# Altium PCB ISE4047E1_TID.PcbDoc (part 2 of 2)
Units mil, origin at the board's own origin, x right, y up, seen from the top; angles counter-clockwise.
Board outline 2952.76 x 1377.95 mil, 4 copper layers (Layer 1 - Top Layer, Layer 2 - GND, Layer 3 - PWR, Layer 4 - Bottom Layer), stack 43.668 mil thick; 130 components, 47 nets, 287 pads, 266 vias.
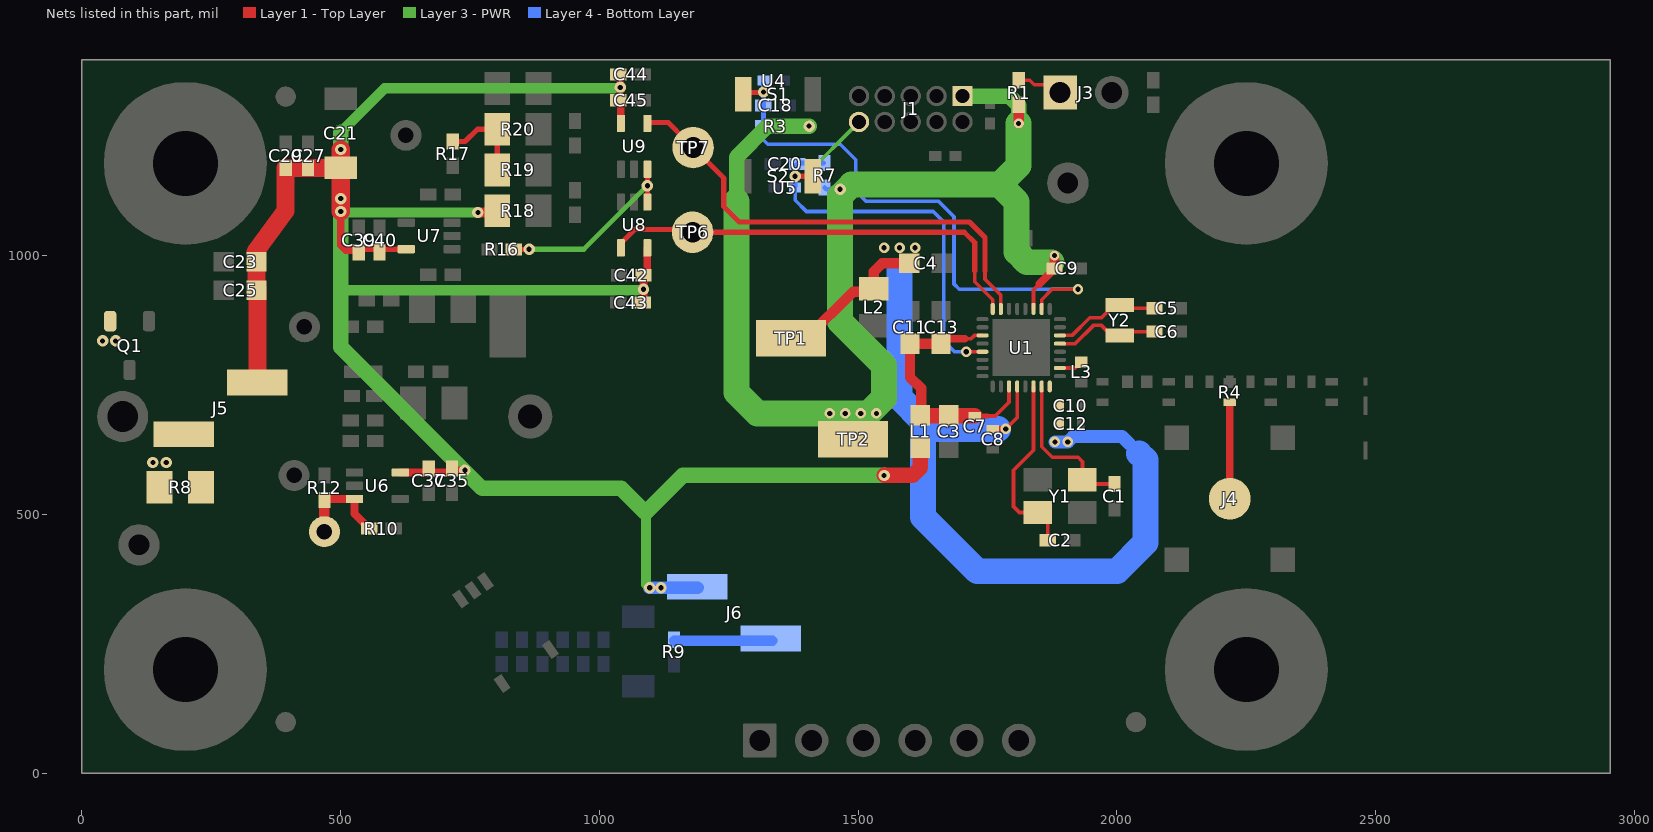
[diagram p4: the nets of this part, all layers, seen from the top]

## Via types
v1: diameter 20, hole 10, Layer 1 - Top Layer to Layer 4 - Bottom Layer, tented both sides, 198 vias
v2: diameter 22, hole 10, Layer 1 - Top Layer to Layer 4 - Bottom Layer, tented both sides, 52 vias
v3: diameter 19.68, hole 7.87, Layer 1 - Top Layer to Layer 4 - Bottom Layer, tented both sides, 16 vias

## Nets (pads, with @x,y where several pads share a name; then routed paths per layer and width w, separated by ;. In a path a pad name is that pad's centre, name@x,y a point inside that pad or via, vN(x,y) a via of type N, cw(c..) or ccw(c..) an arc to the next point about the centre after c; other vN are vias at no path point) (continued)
NetJ3_1: J3.1 R1.1 | length 89.8
  Layer 1 - Top Layer w7: R1.1@1810,1338.62 1831.38,1338.62 1840,1330 1875,1330 J3.1@1890,1315
NetJ4_1: J4.1 R4.2 | length 184.7
  Layer 1 - Top Layer w15: J4.1@2218,531.63 R4.2@2218,716.3
NetJ5_1: J5.1 R8.2
NetJ6_1: J6.1 R9.2 | length 189.6
  Layer 4 - Bottom Layer w20: R9.2@1144,255.69 J6.1@1333.62,255.69
NetL3_1: L3.1 U1.2 | length 45.8
  Layer 1 - Top Layer w7: U1.2@1889.8,782.63 1919.63,782.63 1930.7,793.7 L3.1@1931,793.7
NetQ1_2: Q1.2 R8.1
  other v2: 137,600 163,600 40,835 65,835
NetR10_2: pad.0@468.5,466.39 R10.2 R12.2 U6.3 | length 189
  Layer 1 - Top Layer w15: R12.2@468.5,527.56 470.47,529.53 U6.3@526.57,529.53 526.57,500.98 R10.2@555.12,472.44
  Layer 1 - Top Layer w20: pad.0@468.5,466.39 R12.2@468.5,527.56
NetR16_2: R16.2 U8.1 U9.3 | length 373.9
  Layer 1 - Top Layer w10: R16.2@834.65,1011.81 863.81,1011.81 v2(864,1012) ; U8.1@1092.52,1103.35 v2(1092.52,1135) U9.3@1092.52,1168.31
  Layer 3 - PWR w10: v2(864,1012) 969.52,1012 v2(1092.52,1135)
NetR17_2: R17.2 R19.1 R20.2 | length 174.5
  Layer 1 - Top Layer w10: R17.2@716.54,1220.47 740.47,1220.47 764.09,1244.09 R20.2@802.52,1244.09 R19.1@802.52,1165.35
NRESET: C20.2 J1.10 R7.1 S2.2 U1.21 U5.1 | length 942.4
  Layer 1 - Top Layer w7: v1(1708.75,814.13) U1.21@1740.2,814.13
  Layer 1 - Top Layer w10: v2(1378.09,1153.3) v2(1378.09,1153.3) S2.2@1411.93,1153.26
  Layer 3 - PWR w7: v2(1378.09,1153.3) 1396.53,1153.3 J1.10@1501.42,1258.19
  Layer 4 - Bottom Layer w7: U5.1@1378.05,1133.59 1378.05,1106.95 1400,1085 1645,1085 1665,1065 1665,835 1685.87,814.13 v1(1708.75,814.13)
  Layer 4 - Bottom Layer w10: U5.1@1378.05,1133.59 1378.05,1172.96 1383.96,1178.87 R7.1@1433.17,1178.87
PIR_OUT_HI: TP6.1 U1.16 U8.4 | length 850.4
  Layer 1 - Top Layer w7: 1725,970 1725,949.62 1759.88,914.74 U1.16@1759.88,896.8
  Layer 1 - Top Layer w10: U8.4@1041.34,1014.76 1041.34,1023.66 1067.68,1050 TP6.1@1175.98,1050 ; TP6.1@1180,1045 1705,1045 1725,1025 1725,970
PIR_OUT_LO: TP7.1 U1.15 U9.4 | length 905.8
  Layer 1 - Top Layer w7: 1745,970 1745,954.42 1775.63,923.79 U1.15@1775.63,896.8
  Layer 1 - Top Layer w10: U9.4@1092.52,1256.89 1132.87,1256.89 TP7.1@1165.87,1223.9 ; TP7.1@1181.1,1208.66 1240,1149.76 1240,1095 1270,1065 1715,1065 1745,1035 1745,970
USR_BTN: C18.2 R3.1 S1.2 U1.10 U4.1 | length 1087
  Layer 1 - Top Layer w7: U1.10@1854.37,896.8 1854.37,914.75 1874.62,935 v1(1924.62,935)
  Layer 1 - Top Layer w10: S1.2@1278.07,1312 1281.07,1315 1315.97,1315 v2(1316.97,1316)
  Layer 4 - Bottom Layer w7: R3.1@1316.38,1250 1316.38,1223.62 1325,1215 1465,1215 1495,1185 1495,1125 1515,1105 1655,1105 1685,1075 1685,945 1695,935 v1(1924.62,935)
  Layer 4 - Bottom Layer w10: R3.1@1316.97,1250 v2(1316.97,1316) U4.1@1316.97,1334.41
V_BATT: C21.1 C23.1 C25.1 C27.1 C29.1 C35.2 C37.1 C39.2 C40.1 C42.2 C43.1 C44.2 C45.1 J5.2 J6.2 L1.1 R18.2 U6.5 U7.5 U8.5 U9.5 | length 4605.7
  Layer 1 - Top Layer w10: C39.2@529.17,1010.31 531.13,1012.28 U7.5@626.61,1012.28
  Layer 1 - Top Layer w15: v2(500,1085) 500,1020 509.69,1010.31 C39.2@529.17,1010.31 ; U6.5@615.16,580.71 708.66,580.71 716.54,588.58 720.12,585 v2(740,585) ; R18.2@800.91,1085 R18.2@802.52,1086.61 ; C44.2@1040,1350 v2(1040,1325) 1040,1302.46 1041.85,1300.61 1041.34,1300.1 U9.5@1041.34,1256.89 ; C43.1@1083.62,905 1085,906.38 v2(1085,935) 1085.16,935.16 C42.2@1085.16,962.03 1092.52,969.39 U8.5@1092.52,1014.76
  Layer 1 - Top Layer w20: v2(765,1083.07) 798.98,1083.07 R18.2@802.52,1086.61
  Layer 1 - Top Layer w30: v2(1550,575) 1605,575 1620,590 L1.1@1620,628.5
  Layer 1 - Top Layer w35: 335,1006.89 393.7,1086.61 C29.1@393.7,1169.29 C21.1@500,1169.29 ; C25.1@337.28,933.07 C23.1@337.28,988.19 ; J5.2@339,768 C25.1@339,938.35 ; v2(500,1085) v2(500,1110) C21.1@500,1169.29 ; v2(500,1205) C21.1@500,1169.29
  Layer 3 - PWR w20: 500,933.07 v2@1085,933.07 ; v2@500,1083.07 v2(765,1083.07) ; 500,1238.07 585,1323.07 v2@1040,1323.07 ; v2@1090,365.07 1090,503
  Layer 3 - PWR w30: 500,1238.07 500,1083.07 500,933.07 500,823.07 773.07,550 1042,550 1089,503 1161,575 v2(1550,575)
  Layer 4 - Bottom Layer w25: v2(1097,358.07) v2(1119,358.07) J6.2@1189.14,358.07
VDDR: C4.2 C8.1 C10.1 C12.1 L2.2 TP1.1 U1.28 U1.32 | length 1898.5
  Layer 1 - Top Layer w7: v1(1785,665) 1807.13,687.13 U1.28@1807.13,747.2
  Layer 1 - Top Layer w12: C8.1@1760,665 v1(1785,665)
  Layer 1 - Top Layer w20: TP1.1@1395,840 1400,840 1490,930 1524.57,930 L2.2@1530,935.43 1530,969 1546,985 C4.2@1598.5,985
  Layer 4 - Bottom Layer w25: v1(1880,640) v1(1905,640) 1915,650 2010,650 2042.5,617.5
  Layer 4 - Bottom Layer w50: 1580,970 1580,725 1625,680 ; 1770,665 1640,665 1625,680 ; 2042.5,617.5 2055,605 2055,445 2000,390 1730,390 1625,495 1625,680
  other v1: 1550,1015 1580,1015 1610,1015
VDDS: C3.1 C7.1 C9.1 C11.2 C13.2 J1.1 L1.2 R1.2 R3.2 R7.2 TP2.1 U1.11 U1.19 U1.27 | length 2916.7
  Layer 1 - Top Layer w7: 1706,839 1718,839 1724.62,845.62 U1.19@1740.2,845.62 ; 1750,690 1765,690 1791.38,716.38 U1.27@1791.38,747.2 ; U1.11@1838.62,896.8 1838.62,933.62 1850,945
  Layer 1 - Top Layer w10: C7.1@1725,690 1750,690
  Layer 1 - Top Layer w15: C13.2@1660,829.5 1669.5,839 1706,839 ; 1850,945 1879.38,974.38 C9.1@1879.38,975
  Layer 1 - Top Layer w20: L1.2@1621.5,690 1621.5,743.5 1600,765 C11.2@1600,829.5 C13.2@1660,829.5 ; v1(1810,1255) R1.2@1810,1291.38 ; C9.1@1879.38,975 v1(1879.38,1000)
  Layer 1 - Top Layer w30: L1.2@1621.5,690 C7.1@1725,690
  Layer 3 - PWR w30: 1265,1105 1265,1190 1325,1250 v2(1405,1250) ; J1.1@1701.42,1308.19 1791.81,1308.19 1810,1290 v1(1810,1255)
  Layer 3 - PWR w50: 1265,1105 1265,735 1305,695 1520,695 1550,725 1550,787 1465,872 1465,1115 1487,1137 1773,1137 ; v1(1810,1255) 1810,1174 1773,1137 ; 1874,987 1826,987 1806,1007 1806,1104 1773,1137
  Layer 4 - Bottom Layer w9: R7.2@1435,1131.38 1438.38,1128 v2(1465,1128)
  Layer 4 - Bottom Layer w10: R3.2@1363.62,1250 v2(1405,1250)
  other v1: 1445,695 1475,695 1505,695 1535,695
X24M_N: C2.2 U1.30 Y1.3 | length 361.3
  Layer 1 - Top Layer w7: U1.30@1838.62,747.2 1838.62,623.62 1800,585 1800,515 1811.5,503.5 Y1.3@1846.69,503.5 1866.38,483.82 C2.2@1866.38,450
X24M_P: C1.2 U1.31 Y1.1 | length 307.6
  Layer 1 - Top Layer w7: U1.31@1854.37,747.2 1854.37,630.63 1875,610 1925,610 1933.31,601.69 Y1.1@1933.31,566.5 1941.18,558.62 C1.2@1995,558.62
X32K_Q1: C6.1 U1.5 Y2.1 | length 208
  Layer 1 - Top Layer w7: U1.5@1889.8,829.87 1919.5,829.87 1954.62,865 1969.62,865 ; 1970,865 1989.53,845.47 Y2.1@2005,845.47 2012.53,853 C6.1@2072.38,853
X32K_Q2: C5.1 U1.6 Y2.2 | length 209.3
  Layer 1 - Top Layer w7: U1.6@1889.8,845.62 1912.97,845.62 1947.35,880 1969.62,880 ; 1970,880 1994.53,904.53 Y2.2@2005,904.53 2011.53,898 C5.1@2072.38,898
pads on no net: FID1.1 FID2.1 FID3.1 FID4.1 FID5.1 FID6.1 H1.0 H7.0 J1.6 J1.7 J1.8 SH-J1.0 SH-J2.0 SH-J3.0 U1.4 U1.8 U1.22

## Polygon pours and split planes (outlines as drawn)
GND on Layer 1 - Top Layer "Layer 1 - Top Layer - GND" (solid, remove dead copper, pour order 2): 20,20 2464.57,20 2464.57,1355 20,1355
GND on Layer 2 - GND "Layer 2 - GND - GND" (solid, remove dead copper, pour order 4): 20,20 2464.57,20 2464.57,1355 20,1355
GND on Layer 3 - PWR "Layer 3 - PWR - GND" (solid, remove dead copper, pour order 6): 20,20 2464.57,20 2464.57,1355 20,1355
GND on Layer 4 - Bottom Layer "Layer 4 - Bottom Layer - GND" (solid, remove dead copper, pour order 8): 20,1355 20,20 2464.57,20 2464.57,1355

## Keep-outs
Keep-Out Layer:
  lines w10: -5,0 ccw(c0,0) 0,-5 ; -5,0 ccw(c0,0) 0,-5 ; -5,0 -5,1377.95 ; -5,1377.95 cw(c0,1377.95) 0,1382.95 ; -5,1377.95 cw(c0,1377.95) 0,1382.95 ; 0,-5 2952.76,-5 ; 0,1382.95 2952.76,1382.95 ; 2952.76,-5 ccw(c2952.76,0) 2957.76,0 ; 2952.76,-5 ccw(c2952.76,0) 2957.76,0 ; 2952.76,1382.95 cw(c2952.76,1377.95) 2957.76,1377.95 ; 2952.76,1382.95 cw(c2952.76,1377.95) 2957.76,1377.95 ; 2957.76,0 2957.76,1377.95
  text ".Layer_Name" at 577,-858.49 h60

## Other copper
Layer 1 - Top Layer:
  rectangle net NetBT1_1: 51.18,690 105,800
  rectangle net NetJ5_1: 205,559 255,679
  rectangle net NetQ1_2: 25,820 80,895
  rectangle net NetQ1_2: 125,520 175,611
  pour cut-out: 2050,370 2380,370 2380,695 2050,695
  pour cut-out: 1490,870 1755,870 1755,980 1700,1035 1490,1035
  region net GND: 1578,873 1578,933 1595,950 1625,950 1640,965 1640,1005 1685,1005 1705,985 1705,926 1752,879 1759,879 1762,876 1762,866 1755,873
  pour cut-out: 1727.4,734.8 1902.6,734.8 1902.6,910 1727.4,910
  pour cut-out: 2464.57,0 2952.76,0 2952.76,1377.95 2464.57,1377.95
  region net GND: 1895,435 1895,530 2010,530 2010,455 1990,435
  region net GND: 2464.57,780.77 2464.57,1355 2415,1355 2415,820 1960,820 1960,780.77
  region net GND: 2464.57,20 2415,20 2415,730 2464.57,730
  region net VDDS: 1570,610 1570,650 1585,665 1695,665 1710,680 1710,700 1695,715 1535,715 1445,715 1420,690 1420,610
  region net GND: 2480,604.06 2460.94,604.06 2455,610 2455,635 2462.43,642.43 2480,642.43
  region net GND: 2480,690.68 2459.32,690.68 2455,695 2455,720 2464.05,729.05 2480,729.05
  region net NetC15_1: 1974,744.3 1919,744.3 1919,768.3 1974,768.3
  region net NetC17_1: 2223,744.3 2230,744.3 2230,768.3 2223,768.3
  region net VDDR: 1866,759 1866,639 1875,630 1910,630 1915,635 1915,645 1900,660 1900,731 1872,759
  pour cut-out: 1833,760 1833,678 1785,630 1785,485 1835,435 1990,435 2010,455 2010,590 1985,615 1876,615 1859,632 1859,760 1869,760 1869,636 1880,625 1990,625 2020,595 2020,450 1995,425 1830,425 1775,480 1775,635 1823,683 1823,760 1823,769 1869,769 1869,760
  pour cut-out: 1725,725 1442.76,725 1407.76,690 1407.76,757.76 1485,835 1725,835
  pour cut-out: 2464.57,730 2242,730 2242,572 2240,570 2200,570 2194,576 2194,730 1916,730 1908,738 1908,763 1925.77,780.77 2464.57,780.77
  pour cut-out: 1020,1145 1115,1145 1115,1285 1020,1285
  pour cut-out: 1019.93,993.05 1114.93,993.05 1114.93,1133.05 1019.93,1133.05
  region net VDDR: 1620,965 1620,1020 1615,1025 1545,1025 1500,980 1500,910 1560,910 1560,945 1580,965
  text ".Layer_Name" at 577,-858.49 h60
Layer 2 - GND:
  pour cut-out: 2464.57,0 2952.76,0 2952.76,1377.95 2464.57,1377.95
  region net GND: 1990,435 1835,435 1785,485 1785,630 1815,660 1815,760 1859,760 1859,632 1876,615 1985,615 2010,590 2010,455
  pour cut-out: 1815,760 1815,660 1785,630 1785,485 1835,435 1990,435 2010,455 2010,590 1985,615 1876,615 1859,632 1859,760 1869,760 1869,636 1880,625 1990,625 2020,595 2020,450 1995,425 1830,425 1775,480 1775,635 1805,665 1805,769 1869,769 1869,760
  text ".Layer_Name" at 577,-858.49 h60
Layer 3 - PWR:
  rectangle net V_BATT: 1080,342.93 1134.14,378.07
  pour cut-out: 2464.57,0 2952.76,0 2952.76,1377.95 2464.57,1377.95
  region net NetQ1_2: 25,830 85,770 110,770 150,730 150,650 120,620 120,585 205,585 205,760 110,855 25,855
  pour cut-out: 1815,760 1815,660 1785,630 1785,485 1835,435 1990,435 2010,455 2010,590 1985,615 1876,615 1859,632 1859,760 1869,760 1869,636 1880,625 1990,625 2020,595 2020,450 1995,425 1830,425 1775,480 1775,635 1805,665 1805,769 1869,769 1869,760
  text ".Layer_Name" at 577,-858.49 h60
Layer 4 - Bottom Layer:
  pour cut-out: 2464.57,0 2952.76,0 2952.76,1377.95 2464.57,1377.95
  pour cut-out: 1815,760 1815,660 1785,630 1785,485 1835,435 1990,435 2010,455 2010,590 1985,615 1876,615 1859,632 1859,760 1869,760 1869,636 1880,625 1990,625 2020,595 2020,450 1995,425 1830,425 1775,480 1775,635 1805,665 1805,769 1869,769 1869,760
  region net VDDR: 1560,955 1540,975 1540,1025 1620,1025 1620,975 1600,955
  text ".Layer_Name" at 577,-858.49 h60

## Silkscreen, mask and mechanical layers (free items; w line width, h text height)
Top Overlay:
  text ".TID" at 1399.51,300.82 h60
  text ".PRJ_Number" at 1399.51,249.64 h60
  text ".PCB_Rev" at 1635.73,249.64 h60
  text ".Layer_Name" at 577,-858.49 h60
Bottom Overlay:
  text ".Layer_Name" at 577,-858.49 h60
Top Paste:
  text ".Layer_Name" at 577,-858.49 h60
Bottom Paste:
  text ".Layer_Name" at 577,-858.49 h60
Top Solder:
  text ".Layer_Name" at 577,-858.49 h60
  text ".Layer_Name" at 577,-858.49 h60
Bottom Solder:
  text ".Layer_Name" at 577,-858.49 h60
Drill Guide:
  text ".Layer_Name" at 577,-858.49 h60
M1 Board Outline:
  the board outline again, w10
  text "SLOT" at 980,290 h40 r30.14
  text "SLOT" at 635,90 h40 r30.14
  text ".Layer_Name" at 577,-858.49 h60
M2 Board Dimensions:
  rectangle: 125,-400 500,-275
  rectangle: 0,-275 125,-150
  lines w7: 0,-275 1000,-275 ; 125,-400 125,-150 ; 250,-400 250,-150 ; 500,-400 500,-150 ; 750,-400 750,-150 ; 0,-400 0,-150 1000,-150 1000,-400 0,-400
  text ".Layer_Name" at 577,-858.49 h60
M3 3D STEP Top:
  text ".Layer_Name" at 577,-858.49 h60
M4 3D STEP Bottom:
  text ".Layer_Name" at 577,-858.49 h60
M5 Assembly Top:
  lines w10: -292,-930.17 6308,-930.17 ; -292,-726.83 6310,-726.83 ; -292,-523.5 -292,-1133.5 3713,-1133.5 6310,-1133.5 6310,-523.5 -291.5,-523.5 -291.5,-1133.5 1284,-1133.5 ; 2173,-1133.5 2173,-523.5 ; 3440,-726.83 3440,-523.5 ; 4280,-726.83 4280,-523.5 ; 4902,-1140 4902,-937.17
  text "COMPONENTS MARKED 'DNP' SHOULD NOT BE POPULATED." at 1153.5,-318.5 h60
  text "ASSEMBLY VARIANT:" at 1153,-434 h60
  text ".VariantName" at 2189,-434 h60
  text "PCB VIEWED FROM TOP SIDE" at -228.5,-655.67 h60
  text "BOARD #:" at 2248,-655.67 h60
  text ".PRJ_Number" at 2793.5,-655.67 h60
  text "REV:" at 3638,-655.67 h60
  text ".PCB_Rev" at 3929.5,-655.67 h60
  text "SVN REV:" at 4476,-655.67 h60
  text ".VersionControl_RevNumber" at 4982,-655.67 h60
  text "TID #:" at 2248,-859 h60
  text ".TID" at 2793.5,-859 h60
  text "PLOT NAME =" at -228.5,-1064.34 h60
  text ".plot_File_Name" at 577,-1064.34 h60
  text "GENERATED    :" at 2250,-1064.34 h60
  text ".Print_Date" at 3119.5,-1064.34 h60
  text ".Print_Time" at 3848.5,-1064.34 h60
  text "TEXAS INSTRUMENTS" at 5113,-1064.34 h60
M6 Assembly Bottom:
  lines w10: -292.5,-727.33 6309.5,-727.33 ; -290.5,-930.67 6309.5,-930.67 ; 1115.5,-1140.5 1115.5,-937.67 ; 1737.5,-727.33 1737.5,-524 ; 2577.5,-727.33 2577.5,-524 ; 3844.5,-1134 3844.5,-524 ; 4733.5,-1134 6309,-1134 6309,-524 -292.5,-524 -292.5,-1134 2304.5,-1134 6309.5,-1134 6309.5,-524
  text "COMPONENTS MARKED 'DNP' SHOULD NOT BE POPULATED." at 6102,-318 h60
  text ".VariantName" at 5058,-434 h60
  text "ASSEMBLY VARIANT:" at 6097,-434 h60
  text ".VersionControl_RevNumber" at 1035.5,-656.17 h60
  text "SVN REV:" at 1541.5,-656.17 h60
  text ".PCB_Rev" at 2088,-656.17 h60
  text "REV:" at 2379.5,-656.17 h60
  text ".PRJ_Number" at 3224,-656.17 h60
  text "BOARD #:" at 3769.5,-656.17 h60
  text "PCB VIEWED FROM BOTTOM SIDE" at 6246,-656.17 h60
  text ".TID" at 3224,-859.5 h60
  text "TID #:" at 3769.5,-859.5 h60
  text "TEXAS INSTRUMENTS" at 904.5,-1064.84 h60
  text ".Print_Time" at 2169,-1064.84 h60
  text ".Print_Date" at 2898,-1064.84 h60
  text "GENERATED    :" at 3767.5,-1064.84 h60
  text ".plot_File_Name" at 5440.5,-1064.84 h60
  text "PLOT NAME =" at 6246,-1064.84 h60
M9 Title Sheet:
  drawing of 57 lines, arcs and shapes, not listed
  text "1" at 739.84,8036.5 h70
  text "2" at 3235.5,8036.5 h70
  text "3" at 5724.84,8036.5 h70
  text "4" at 8231.51,8036.5 h70
  text "5" at 10730.5,8036.5 h70
  text "6" at 13235.5,8036.5 h70
  text "A" at -416.5,6893.5 h70
  text "A" at 14383.5,6893.5 h70
  text "B" at -416.5,4513.5 h70
  text "B" at 14383.5,4513.5 h70
  text "C" at -416.5,2138.5 h70
  text "C" at 14383.5,2138.5 h70
  text "PROJECT TITLE:" at 11343.5,277.5 h45
  text ".PRJ_Title" at 11393.5,144.17 h70
  text "DESIGNED FOR:" at 11343.5,-23.5 h45
  text ".PRJ_Customer" at 11393.5,-163.5 h70
  text "D" at -416.5,-231.5 h70
  text "D" at 14383.5,-231.5 h70
  text "FILE NAME:" at 11343.5,-323.5 h45
  text ".PCB_File_Name_No_Path" at 11393.5,-443.5 h70
  text "Texas Instruments (TI) and/or its licensors do not warrant the accuracy or completeness of this specification" at 6374,-605.34 h45
  text "ENGINEER:" at 11343.5,-613.5 h45
  text "LAYOUT BY:" at 12848.5,-613.5 h45
  text "or any information contained therein. TI and/or its licensors do not warrant that this design will meet" at 6329.01,-718 h45
  text ".PRJ_Engineer" at 11393.5,-768.49 h70
  text ".PCB_Layout" at 12899,-768.49 h70
  text "the specifications, will be suitable for your application or fit for any particular purpose, or will operate in" at 6329.01,-830.67 h45
  text ".Layer_Name" at 577,-858.49 h60
  text "ALTIUM DESIGNER VERSION:" at 12848.5,-923.5 h45
  text "an implementation. TI and/or its licensors do not warrant that the design is production worthy. You should" at 6329.01,-943.33 h45
  text "completely validate and test your design implementation to confirm the system functionality for your application." at 6374,-1056 h45
  text ".print_Scale" at 11393.5,-1056.83 h70
  text ".Application_BuildNumber" at 12899,-1056.83 h70
  text "1" at 739.84,-1263.5 h70
  text "2" at 3235.5,-1263.5 h70
  text "3" at 5724.84,-1263.5 h70
  text "4" at 8231.51,-1263.5 h70
  text "5" at 10730.5,-1263.5 h70
  text "6" at 13235.5,-1263.5 h70
M10 Fab Notes:
  drawing of 186 lines, arcs and shapes, not listed
  text "DESIGN INFORMATION" at 12381.02,5910 h60
  text "MIN. TRACK WIDTH:" at 11736.46,5730 h60
  text "6" at 12832.7,5730 h60
  text "MIL" at 12987.46,5730 h60
  text "Impedance Control:" at 6857,5615 h200
  text "MIN. CLEARANCE:" at 11736.46,5598 h60
  text "mm" at 12987.46,5598 h60
  text "6" at 12830,5595 h60
  text "MIN. VIA PAD SIZE:" at 11736.46,5466 h60
  text "20" at 12802.71,5466 h60
  text "MIL" at 12987.46,5466 h60
  text "- Top layer contains 50 ohm impedance (+/- 10%) single ended using 24 mil lines (from E1 to U1)" at 6857,5375 h100
  text "0.05mm (2MIL)" at 12431.46,5324.29 h60
  text "MINIMUM ANNULAR RING" at 11407.23,5320 h60
  text "EXTERNAL" at 13139.46,5320 h60
  text "PER" at 11607.23,5202 h60
  text "IPC-D-275 CLASS 2 LEVEL C" at 11827.23,5202 h60
  text "MIL, HOLES" at 13315.46,5089.71 h60
  text "+/-" at 12923,5089 h60
  text "+/-" at 13777,5089 h60
  text "REGISTRATION TOLERANCES:" at 11407.23,5084 h60
  text "METAL" at 12607,5084 h60
  text "5" at 13183.2,5084 h60
  text "3" at 14016.2,5084 h60
  text "MIL" at 14132.46,5084 h60
  text "MATERIAL:" at 11332.46,4874.54 h60
  text "FR-4 High Tg" at 12318.9,4734.21 h60
  text "FR-408" at 11753.46,4725.64 h60
  text "X" at 12165.46,4725.64 h60
  text "OTHER" at 13241.46,4725.64 h60
  text "62 MIL (1.6mm) +/-10%" at 12073.56,4562.92 h60
  text "THICKNESS:" at 11407.23,4558.64 h60
  text "31 MIL (0.8mm) +/-10%" at 13348.56,4557.92 h60
  text "X" at 13230,4550 h60
  text "TOLERANCE:" at 11407.23,4400.64 h60
  text "X" at 12246.53,4400.64 h60
  text "ANSI IPC-6012 TYPE 3 CLASS 2" at 12433.48,4400.64 h60
  text "OTHER +/-" at 12433.46,4244.64 h60
  text "BOW & TWIST:" at 11407.23,4087.64 h60
  text "X" at 12246.53,4087.64 h60
  text "ANSI IPC-6012 TYPE 3 CLASS 2" at 12433.48,4087.64 h60
  text "OTHER +/-" at 12433.46,3929.13 h60
  text "DRILLING:" at 11332.46,3790.64 h60
  text "REFERENCE:" at 11407.23,3673.64 h60
  text "X" at 12055.46,3673.64 h60
  text "AS SHOWN" at 12242.46,3673.64 h60
  text "X" at 12956.46,3673.64 h60
  text "NC_DRILL FILES" at 13093.46,3673.64 h60
  text "PTH MIN COPPER THICKNESS:" at 11407.23,3515.64 h60
  text "X" at 12757.46,3515.64 h60
  text "1MIL" at 12894.46,3515.64 h60
  text "OTHER" at 13391.46,3515.64 h60
  text "BOARD FINISH:" at 11332.46,3356.64 h60
  text "SILKSCREEN:" at 11487.68,3238.64 h60
  text "X" at 12436.46,3238.64 h60
  text "TOP" at 12562.46,3238.64 h60
  text "X" at 12946.46,3238.64 h60
  text "BOTTOM" at 13073.46,3238.64 h60
  text "SILKSCREEN COLOR:" at 11487.68,3071.64 h60
  text "X" at 12435.42,3071.64 h60
  text "WHITE" at 12562.46,3071.64 h60
  text "OTHER" at 13073.46,3071.64 h60
  text "SOLDER RESIST COLOR:" at 11487.68,2901.64 h60
  text "X" at 12055.42,2742.44 h60
  text "GREEN" at 12182.46,2742.44 h60
  text "BLUE" at 12773.46,2742.44 h60
  text "OTHER" at 13311.46,2742.44 h60
  text "IMMERSION GOLD (ENIG)" at 12393.46,2553.92 h60
  text "ENEPIG" at 13731,2550.64 h60
  text "SURFACE FINISH:" at 11332.46,2549.64 h60
  text "X" at 12206.51,2549.64 h60
  text "IMM. TIN/SILVER OR EQUIV" at 11662,2392.64 h60
  text "OTHER" at 13093.46,2392.64 h60
  text "ARRAY/PANEL:" at 11332.46,2213.64 h60
  text "CUT AND TRIM PER MECH LAYER 1" at 12393.46,2209.35 h60
  text "N.C. ROUTE" at 12393.46,2057.64 h60
  text "X" at 13072.46,2057.64 h60
  text "V. SCORE" at 13259.46,2057.64 h60
  text "CERTIFICATION:" at 11332.46,1920.64 h60
  text "MATERIALS AND WORKMANSHIP FOR ALL PCBS" at 12057.46,1920.64 h60
  text "TO MEET OR EXCEED THE REQUIREMENTS OF:" at 12057.46,1822.64 h60
  text "X" at 11683.96,1686.13 h60
  text "ANSI IPC-A-600F CLASS ->" at 11822.96,1686.13 h60
  text "X" at 13462.02,1686.13 h60
  text "2" at 13580.96,1686.14 h60
  text "1" at 13265.96,1684.64 h60
  text "3" at 13934.96,1684.64 h60
  text "X" at 11686.02,1526.64 h60
  text "UL 94V-0" at 11822.96,1526.64 h60
  text "X" at 12498.02,1526.64 h60
  text "RoHS" at 12634.96,1526.64 h60
  text "OTHER" at 13279.36,1526.64 h60
  text "PER ORDER" at 13676.42,1526.64 h60
  text "ADDITIONAL REQUIREMENTS:" at 11332.46,1385.64 h60
  text "MICROSECTION:" at 11407.23,1270.64 h60
  text "YES" at 12312.96,1270.64 h60
  text "REQUIRED" at 13174.46,1114.49 h60
  text "BARE BOARD ELEC. TEST:" at 11407.23,1111.64 h60
  text "NONE" at 12712.96,1111.64 h60
  text "X" at 13047.46,1111.64 h60
  text "PER ORDER" at 13766.46,1111.64 h60
  text "MANUFACTURER'S UL:" at 11407.23,954.64 h60
  text "RAIL" at 12572.96,950.35 h60
  text "METAL" at 13064.77,950.35 h60
  text "X" at 13440,950 h60
  text "SILK" at 13576.46,950.35 h60
  text ".Layer_Name" at 577,-858.49 h60
M11 Gerber Information:
  lines w10: -292,-930.17 6308,-930.17 ; -292,-726.83 6310,-726.83 ; -292,-523.5 -292,-1133.5 3713,-1133.5 6310,-1133.5 6310,-523.5 -291.5,-523.5 -291.5,-1133.5 1284,-1133.5 ; 2173,-1133.5 2173,-523.5 ; 3440,-726.83 3440,-523.5 ; 4280,-726.83 4280,-523.5 ; 4902,-1140 4902,-937.17
  text "ALL ARTWORK VIEWED FROM TOP SIDE" at -228.5,-655.67 h60
  text "BOARD #:" at 2248,-655.67 h60
  text ".PRJ_Number" at 2793.5,-655.67 h60
  text "REV:" at 3638,-655.67 h60
  text ".PCB_Rev" at 3929.5,-655.67 h60
  text "SVN REV:" at 4476,-655.67 h60
  text ".VersionControl_RevNumber" at 4982,-655.67 h60
  text "LAYER NAME =" at -228.5,-858.49 h60
  text "TID #:" at 2248,-859 h60
  text ".TID" at 2793.5,-859 h60
  text "PLOT NAME =" at -228.5,-1064.34 h60
  text ".plot_File_Name" at 577,-1064.34 h60
  text "GENERATED    :" at 2250,-1064.34 h60
  text ".Print_Date" at 3119.5,-1064.34 h60
  text ".Print_Time" at 3848.5,-1064.34 h60
  text "TEXAS INSTRUMENTS" at 5113,-1064.34 h60
M12 Stackup:
  drawing of 295 lines, arcs and shapes, not listed
  text "Layer" at 9315,7840 h60
  text "Name" at 9724.91,7840 h60
  text "Material" at 11134.5,7840 h60
  text "Thickness" at 11994.27,7840 h60
  text "Constant" at 12644.1,7840 h60
  text "Board Layer Stack" at 13213.97,7840 h60
  text "1" at 9315,7720 h60
  text "Top Overlay" at 9724.91,7720 h60
  text "2" at 9315,7600 h60
  text "Top Solder" at 9724.91,7600 h60
  text "Solder Resist" at 11134.5,7600 h60
  text "0.40mil" at 11994.27,7600 h60
  text "3.5" at 12644.1,7600 h60
  text "3" at 9315,7480 h60
  text "Layer 1 - Top Layer" at 9724.91,7480 h60
  text "Copper" at 11134.5,7480 h60
  text "1.42mil" at 11994.27,7480 h60
  text "4" at 9315,7360 h60
  text "Dielectric 1" at 9724.91,7360 h60
  text "370HR" at 11134.5,7360 h60
  text "14.00mil" at 11994.27,7360 h60
  text "4.2" at 12644.1,7360 h60
  text "5" at 9315,7240 h60
  text "Layer 2 - GND" at 9724.91,7240 h60
  text "Copper" at 11134.5,7240 h60
  text "1.42mil" at 11994.27,7240 h60
  text "6" at 9315,7120 h60
  text "Dielectric 2" at 9724.91,7120 h60
  text "370HR" at 11134.5,7120 h60
  text "10.00mil" at 11994.27,7120 h60
  text "4.2" at 12644.1,7120 h60
  text "7" at 9315,7000 h60
  text "Layer 3 - PWR" at 9724.91,7000 h60
  text "Copper" at 11134.5,7000 h60
  text "1.42mil" at 11994.27,7000 h60
  text "8" at 9315,6880 h60
  text "Dielectric 3" at 9724.91,6880 h60
  text "370HR" at 11134.5,6880 h60
  text "14.00mil" at 11994.27,6880 h60
  text "4.2" at 12644.1,6880 h60
  text "9" at 9315,6760 h60
  text "Layer 4 - Bottom Layer" at 9724.91,6760 h60
  text "Copper" at 11134.5,6760 h60
  text "1.42mil" at 11994.27,6760 h60
  text "10" at 9315,6640 h60
  text "Bottom Solder" at 9724.91,6640 h60
  text "Solder Resist" at 11134.5,6640 h60
  text "0.40mil" at 11994.27,6640 h60
  text "3.5" at 12644.1,6640 h60
  text "11" at 9315,6520 h60
  text "Bottom Overlay" at 9724.91,6520 h60
  text ".Layer_Name" at 577,-858.49 h60
M13 Component Bodies Top:
  text ".Layer_Name" at 577,-858.49 h60
M14 Component Bodies Bottom:
  text ".Layer_Name" at 577,-858.49 h60
M15 Courtyards Top:
  text ".Layer_Name" at 577,-858.49 h60
M16 Courtyards Bottom:
  text ".Layer_Name" at 577,-858.49 h60
Drill Drawing:
  circle w1: c3447.72,1276.04 r24.89
  lines w1: 3422.83,205.92 3472.6,205.92 3472.6,255.69 3422.83,255.69 3422.83,205.92 ; 3422.83,380.12 3447.72,355.24 3472.6,380.12 3447.72,405.01 3422.83,380.12 ; 3422.83,504.56 3422.83,517 3435.27,529.44 3422.83,541.89 3422.83,554.33 3435.27,554.33 3447.72,541.89 3460.16,554.33 3472.6,554.33 3472.6,541.89 3460.16,529.44 3472.6,517 3472.6,504.56 3460.16,504.56 3447.72,517 3435.27,504.56 3422.83,504.56 ; 3422.83,666.32 3435.27,666.32 3435.27,653.88 3460.16,653.88 3460.16,666.32 3472.6,666.32 3472.6,691.21 3460.16,691.21 3460.16,703.65 3435.27,703.65 3435.27,691.21 3422.83,691.21 3422.83,666.32 ; 3422.83,803.2 3447.72,815.64 3472.6,803.2 3460.16,828.08 3472.6,852.97 3447.72,840.53 3422.83,852.97 3435.27,828.08 3422.83,803.2 ; 3422.83,964.96 3435.27,964.96 3447.72,952.52 3460.16,964.96 3472.6,964.96 3460.16,977.4 3472.6,989.85 3460.16,989.85 3447.72,1002.29 3435.27,989.85 3422.83,989.85 3435.27,977.4 3422.83,964.96 ; 3422.83,1151.61 3472.6,1151.61 3447.72,1101.84 3422.83,1151.61 ; 3432.78,1141.65 3462.65,1141.65 3447.72,1111.79 3432.78,1141.65
  lines w12: 3355,161.12 5473.02,161.12 ; 3355,1355.68 5473.02,1355.68 ; 3725.36,11.8 3725.36,1505 ; 4082.36,11.8 4082.36,1505 ; 4743.93,11.8 4743.93,1505 ; 5028.07,11.8 5028.07,1505 ; 3355,11.8 5473.02,11.8 5473.02,1505 3355,1505 3355,11.8
  text "Symbol" at 3444.59,1400.48 h72
  text "Quantity" at 3770.16,1400.48 h72
  text "Finished Hole Size" at 4127.16,1400.48 h72
  text "Plated" at 4788.72,1400.48 h72
  text "Hole Type" at 5072.86,1400.48 h72
  text "16" at 3770.16,1251.16 h60
  text "7.87mil (0.200mm)" at 4127.16,1251.16 h60
  text "PTH" at 4788.72,1251.16 h60
  text "Round" at 5072.86,1251.16 h60
  text "250" at 3770.16,1101.84 h60
  text "10.00mil (0.254mm)" at 4127.16,1101.84 h60
  text "PTH" at 4788.72,1101.84 h60
  text "Round" at 5072.86,1101.84 h60
  text "10" at 3770.16,952.52 h60
  text "27.56mil (0.700mm)" at 4127.16,952.52 h60
  text "PTH" at 4788.72,952.52 h60
  text "Round" at 5072.86,952.52 h60
  text "4" at 3770.16,803.2 h60
  text "30.00mil (0.762mm)" at 4127.16,803.2 h60
  text "PTH" at 4788.72,803.2 h60
  text "Round" at 5072.86,803.2 h60
  text "12" at 3770.16,653.88 h60
  text "40.00mil (1.016mm)" at 4127.16,653.88 h60
  text "PTH" at 4788.72,653.88 h60
  text "Round" at 5072.86,653.88 h60
  text "1" at 3770.16,504.56 h60
  text "46.50mil (1.181mm)" at 4127.16,504.56 h60
  text "PTH" at 4788.72,504.56 h60
  text "Round" at 5072.86,504.56 h60
  text "1" at 3770.16,355.24 h60
  text "59.06mil (1.500mm)" at 4127.16,355.24 h60
  text "PTH" at 4788.72,355.24 h60
  text "Round" at 5072.86,355.24 h60
  text "4" at 3770.16,205.92 h60
  text "125.98mil (3.200mm)" at 4127.16,205.92 h60
  text "PTH" at 4788.72,205.92 h60
  text "Round" at 5072.86,205.92 h60
  text "298 Total" at 3770.16,56.6 h60
  text ".Layer_Name" at 577,-858.49 h60

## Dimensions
0,0 to 2952.76,0 on M2 Board Dimensions
0,0 to 0,1377.95 on M2 Board Dimensions
0,-400 to 1000,-400 on M2 Board Dimensions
